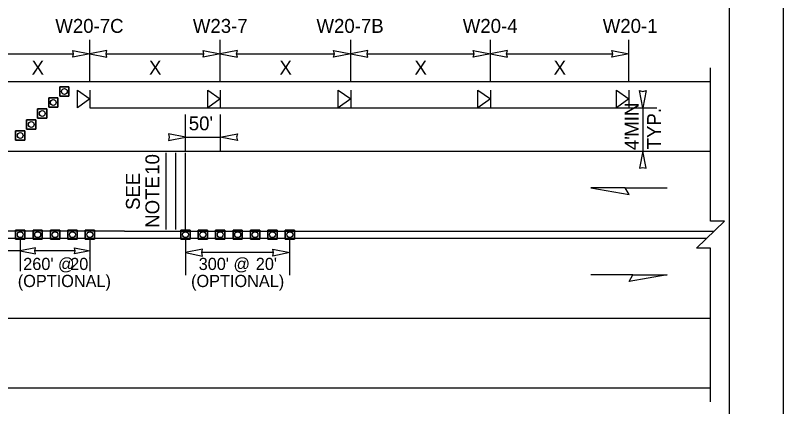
# Model space of a CAD drawing. Extents: x 99999.1 to 100095.7, y 99995 to 100010.7.
# Drawn here: x 100011.645 to 100016.062, y 100005.624 to 100007.873 of the extents above; entities that cross this region are included whole.
import ezdxf

# ---------------------------------------------------------------- set-up
doc = ezdxf.new("R2010")
doc.units = 0
for name, color, linetype in [('RD_ED_ShoulderPavedEdge', 7, 'Continuous'), ('RD_MK_LineDblYellowCenter', 7, 'Continuous'), ('RD_MK_LineEdgeWhite', 7, 'Continuous'), ('RD_MK_LineNoPass', 7, 'Continuous'), ('RD_MK_LineSkipCenter', 7, 'Continuous'), ('SH_GI_PlotLimits', 7, 'Continuous'), ('SH_GI_SheetBorder', 7, 'Continuous'), ('TR_SN_ConstructionSigns', 7, 'Continuous'), ('TR_WZ_PortableSignMountBlk-Org', 7, 'Continuous'), ('TR_WZ_TrafficCone', 7, 'Continuous'), ('TR_WZ_WorkZoneDetails', 7, 'Continuous'), ('TR_WZ_WorkZoneTextCurrent', 7, 'Continuous')]:
    doc.layers.add(name, color=color, linetype=linetype)

msp = doc.modelspace()

# ---------------------------------------------------------------- linework, layer by layer
at = {"layer": 'RD_ED_ShoulderPavedEdge'}
for p, q in [((100000.1076, 100007.4923), (100015.6424, 100007.4923)), ((100000.1076, 100005.7323), (100015.6424, 100005.7323))]:
    msp.add_line(p, q, dxfattribs=at)
at = {"layer": 'RD_MK_LineDblYellowCenter'}
for p, q in [((100012.2733, 100006.6323), (100015.6631, 100006.6323)), ((100012.2733, 100006.5923), (100015.6218, 100006.5923))]:
    msp.add_line(p, q, dxfattribs=at)
at = {"layer": 'RD_MK_LineEdgeWhite'}
for p, q in [((100000.1076, 100007.0923), (100015.6424, 100007.0923)), ((100000.1076, 100006.1323), (100015.6424, 100006.1323))]:
    msp.add_line(p, q, dxfattribs=at)
at = {"layer": 'RD_MK_LineNoPass'}
msp.add_line((100011.4733, 100006.5923), (100012.2733, 100006.5923), dxfattribs=at)
at = {"layer": 'RD_MK_LineSkipCenter'}
msp.add_lwpolyline([(100012.2733, 100006.6323), (100011.4733, 100006.6323)], dxfattribs=at)
at = {"layer": 'SH_GI_PlotLimits'}
msp.add_lwpolyline([(99999.0625, 99999.6875), (100016.0625, 99999.6875), (100016.0625, 100010.6875), (99999.0625, 100010.6875)], close=True, dxfattribs=at)
at = {"layer": 'SH_GI_SheetBorder'}
msp.add_line((100015.75, 100010.375), (100015.75, 100000), dxfattribs=at)
at = {"layer": 'TR_WZ_PortableSignMountBlk-Org'}
for p, q in [((100012.0733, 100007.4422), (100012.0733, 100007.3422)), ((100012.8233, 100007.4422), (100012.8233, 100007.3422)), ((100013.5733, 100007.4422), (100013.5733, 100007.3422)), ((100014.3761, 100007.4422), (100014.3761, 100007.3422)), ((100015.1733, 100007.4422), (100015.1733, 100007.3422))]:
    msp.add_line(p, q, dxfattribs=at)
for points in [[(100012.0733, 100007.3923), (100012.0015, 100007.3422), (100012.0015, 100007.4422)], [(100012.8233, 100007.3923), (100012.7515, 100007.3422), (100012.7515, 100007.4422)], [(100013.5733, 100007.3923), (100013.5015, 100007.3422), (100013.5015, 100007.4422)], [(100014.3761, 100007.3923), (100014.3042, 100007.3422), (100014.3042, 100007.4422)], [(100015.1733, 100007.3923), (100015.1015, 100007.3422), (100015.1015, 100007.4422)]]:
    msp.add_lwpolyline(points, close=True, dxfattribs=at)
at = {"layer": 'TR_WZ_TrafficCone'}
for points in [[(100011.9533, 100007.4623), (100011.9, 100007.4623), (100011.9, 100007.409), (100011.9533, 100007.409), (100011.9533, 100007.4623)], [(100011.9533, 100007.409), (100011.9, 100007.409), (100011.9, 100007.4623), (100011.9533, 100007.4623), (100011.9533, 100007.409)], [(100011.89, 100007.399), (100011.8367, 100007.399), (100011.8367, 100007.3457), (100011.89, 100007.3457), (100011.89, 100007.399)], [(100011.89, 100007.3457), (100011.8367, 100007.3457), (100011.8367, 100007.399), (100011.89, 100007.399), (100011.89, 100007.3457)], [(100011.8267, 100007.3357), (100011.7733, 100007.3357), (100011.7733, 100007.2823), (100011.8267, 100007.2823), (100011.8267, 100007.3357)], [(100011.8267, 100007.2823), (100011.7733, 100007.2823), (100011.7733, 100007.3357), (100011.8267, 100007.3357), (100011.8267, 100007.2823)], [(100011.7633, 100007.219), (100011.71, 100007.219), (100011.71, 100007.2723), (100011.7633, 100007.2723), (100011.7633, 100007.219)], [(100011.7633, 100007.2723), (100011.71, 100007.2723), (100011.71, 100007.219), (100011.7633, 100007.219), (100011.7633, 100007.2723)], [(100011.7, 100007.1557), (100011.6467, 100007.1557), (100011.6467, 100007.209), (100011.7, 100007.209), (100011.7, 100007.1557)], [(100011.7, 100007.209), (100011.6467, 100007.209), (100011.6467, 100007.1557), (100011.7, 100007.1557), (100011.7, 100007.209)], [(100011.7, 100006.639), (100011.6467, 100006.639), (100011.6467, 100006.5857), (100011.7, 100006.5857), (100011.7, 100006.639)], [(100011.7, 100006.5857), (100011.6467, 100006.5857), (100011.6467, 100006.639), (100011.7, 100006.639), (100011.7, 100006.5857)], [(100011.8, 100006.639), (100011.7467, 100006.639), (100011.7467, 100006.5857), (100011.8, 100006.5857), (100011.8, 100006.639)], [(100011.8, 100006.5857), (100011.7467, 100006.5857), (100011.7467, 100006.639), (100011.8, 100006.639), (100011.8, 100006.5857)], [(100011.9, 100006.639), (100011.8467, 100006.639), (100011.8467, 100006.5857), (100011.9, 100006.5857), (100011.9, 100006.639)], [(100011.9, 100006.5857), (100011.8467, 100006.5857), (100011.8467, 100006.639), (100011.9, 100006.639), (100011.9, 100006.5857)], [(100012, 100006.639), (100011.9467, 100006.639), (100011.9467, 100006.5857), (100012, 100006.5857), (100012, 100006.639)], [(100012, 100006.5857), (100011.9467, 100006.5857), (100011.9467, 100006.639), (100012, 100006.639), (100012, 100006.5857)], [(100012.1, 100006.639), (100012.0467, 100006.639), (100012.0467, 100006.5857), (100012.1, 100006.5857), (100012.1, 100006.639)], [(100012.1, 100006.5857), (100012.0467, 100006.5857), (100012.0467, 100006.639), (100012.1, 100006.639), (100012.1, 100006.5857)], [(100012.65, 100006.5857), (100012.5967, 100006.5857), (100012.5967, 100006.639), (100012.65, 100006.639), (100012.65, 100006.5857)], [(100012.65, 100006.639), (100012.5967, 100006.639), (100012.5967, 100006.5857), (100012.65, 100006.5857), (100012.65, 100006.639)], [(100012.75, 100006.5857), (100012.6967, 100006.5857), (100012.6967, 100006.639), (100012.75, 100006.639), (100012.75, 100006.5857)], [(100012.75, 100006.639), (100012.6967, 100006.639), (100012.6967, 100006.5857), (100012.75, 100006.5857), (100012.75, 100006.639)], [(100012.85, 100006.5857), (100012.7967, 100006.5857), (100012.7967, 100006.639), (100012.85, 100006.639), (100012.85, 100006.5857)], [(100012.85, 100006.639), (100012.7967, 100006.639), (100012.7967, 100006.5857), (100012.85, 100006.5857), (100012.85, 100006.639)], [(100012.95, 100006.5857), (100012.8967, 100006.5857), (100012.8967, 100006.639), (100012.95, 100006.639), (100012.95, 100006.5857)], [(100012.95, 100006.639), (100012.8967, 100006.639), (100012.8967, 100006.5857), (100012.95, 100006.5857), (100012.95, 100006.639)], [(100013.05, 100006.5857), (100012.9967, 100006.5857), (100012.9967, 100006.639), (100013.05, 100006.639), (100013.05, 100006.5857)], [(100013.05, 100006.639), (100012.9967, 100006.639), (100012.9967, 100006.5857), (100013.05, 100006.5857), (100013.05, 100006.639)], [(100013.15, 100006.5857), (100013.0967, 100006.5857), (100013.0967, 100006.639), (100013.15, 100006.639), (100013.15, 100006.5857)], [(100013.15, 100006.639), (100013.0967, 100006.639), (100013.0967, 100006.5857), (100013.15, 100006.5857), (100013.15, 100006.639)], [(100013.25, 100006.5857), (100013.1967, 100006.5857), (100013.1967, 100006.639), (100013.25, 100006.639), (100013.25, 100006.5857)], [(100013.25, 100006.639), (100013.1967, 100006.639), (100013.1967, 100006.5857), (100013.25, 100006.5857), (100013.25, 100006.639)]]:
    msp.add_lwpolyline(points, dxfattribs=at)
for centre in [(100011.9267, 100007.4357), (100011.8633, 100007.3723), (100011.8, 100007.309), (100011.7367, 100007.2457), (100011.6733, 100007.1823), (100011.6733, 100006.6123), (100011.7733, 100006.6123), (100011.8733, 100006.6123), (100011.9733, 100006.6123), (100012.0733, 100006.6123), (100012.6233, 100006.6123), (100012.7233, 100006.6123), (100012.8233, 100006.6123), (100012.9233, 100006.6123), (100013.0233, 100006.6123), (100013.1233, 100006.6123), (100013.2233, 100006.6123)]:
    msp.add_circle(centre, 0.0167, dxfattribs=at)
at = {"layer": 'TR_WZ_WorkZoneDetails'}
for p, q in [((100012.0733, 100007.4923), (100012.0733, 100007.7323)), ((100012.8233, 100007.4923), (100012.8233, 100007.7323)), ((100013.5733, 100007.4923), (100013.5733, 100007.7323)), ((100014.3761, 100007.4923), (100014.3761, 100007.7323)), ((100015.1733, 100007.4921), (100015.1733, 100007.7323)), ((100011.5671, 100007.6523), (100011.9796, 100007.6523)), ((100012.1671, 100007.6523), (100012.7296, 100007.6523)), ((100012.9171, 100007.6523), (100013.4796, 100007.6523)), ((100013.6671, 100007.6523), (100014.2823, 100007.6523)), ((100014.4698, 100007.6523), (100015.0796, 100007.6523)), ((100012.0733, 100007.3422), (100015.1733, 100007.3422)), ((100015.1733, 100007.3422), (100015.3333, 100007.3422)), ((100015.2533, 100007.3422), (100015.2533, 100007.0923)), ((100012.6233, 100007.0923), (100012.6233, 100007.3023)), ((100012.8233, 100007.3023), (100012.8233, 100007.0923)), ((100012.6233, 100007.1723), (100012.8233, 100007.1723)), ((100012.5128, 100006.6423), (100012.5128, 100007.0823)), ((100012.5685, 100006.6423), (100012.5685, 100007.0823)), ((100012.6233, 100006.6423), (100012.6233, 100007.0823)), ((100015.1733, 100007.0923), (100015.3333, 100007.0923)), ((100015.1513, 100006.8816), (100015.3924, 100006.8816)), ((100011.6733, 100006.5857), (100011.6733, 100006.4023)), ((100012.0733, 100006.5857), (100012.0733, 100006.4023)), ((100012.6233, 100006.589), (100012.6233, 100006.379)), ((100013.2233, 100006.379), (100013.2233, 100006.589)), ((100011.6733, 100006.5193), (100011.4933, 100006.5193)), ((100011.989, 100006.5193), (100011.7577, 100006.5193)), ((100013.1296, 100006.509), (100012.7171, 100006.509)), ((100015.1959, 100006.3816), (100014.9548, 100006.3816))]:
    msp.add_line(p, q, dxfattribs=at)
for points in [[(100012.0733, 100007.6523), (100011.9751, 100007.6331), (100011.9796, 100007.6523), (100011.9751, 100007.6716)], [(100012.0733, 100007.6523), (100012.1716, 100007.6331), (100012.1671, 100007.6523), (100012.1716, 100007.6716)], [(100012.8233, 100007.6523), (100012.7251, 100007.6331), (100012.7296, 100007.6523), (100012.7251, 100007.6716)], [(100012.8233, 100007.6523), (100012.9216, 100007.6331), (100012.9171, 100007.6523), (100012.9216, 100007.6716)], [(100013.5733, 100007.6523), (100013.4751, 100007.6331), (100013.4796, 100007.6523), (100013.4751, 100007.6716)], [(100013.5733, 100007.6523), (100013.6716, 100007.6331), (100013.6671, 100007.6523), (100013.6716, 100007.6716)], [(100014.3761, 100007.6523), (100014.2778, 100007.6331), (100014.2823, 100007.6523), (100014.2778, 100007.6716)], [(100014.3761, 100007.6523), (100014.4743, 100007.6331), (100014.4698, 100007.6523), (100014.4743, 100007.6716)], [(100015.1733, 100007.6523), (100015.0751, 100007.6331), (100015.0796, 100007.6523), (100015.0751, 100007.6716)], [(100015.2533, 100007.3422), (100015.2341, 100007.4405), (100015.2533, 100007.436), (100015.2726, 100007.4405)], [(100012.6233, 100007.1723), (100012.5251, 100007.1916), (100012.5296, 100007.1723), (100012.5251, 100007.1531)], [(100012.8233, 100007.1723), (100012.9216, 100007.1916), (100012.9171, 100007.1723), (100012.9216, 100007.1531)], [(100015.2533, 100007.0923), (100015.2341, 100006.9941), (100015.2533, 100006.9986), (100015.2726, 100006.9941)], [(100014.9548, 100006.8816), (100015.1736, 100006.843), (100015.1513, 100006.8816)], [(100011.6733, 100006.5193), (100011.7618, 100006.502), (100011.7577, 100006.5193), (100011.7618, 100006.5367)], [(100012.0733, 100006.5193), (100011.9849, 100006.502), (100011.989, 100006.5193), (100011.9849, 100006.5367)], [(100012.6233, 100006.509), (100012.7216, 100006.4897), (100012.7171, 100006.509), (100012.7216, 100006.5283)], [(100013.2233, 100006.509), (100013.1251, 100006.4897), (100013.1296, 100006.509), (100013.1251, 100006.5283)], [(100015.3924, 100006.3816), (100015.1736, 100006.343), (100015.1959, 100006.3816)]]:
    msp.add_lwpolyline(points, close=True, dxfattribs=at)
msp.add_lwpolyline([(100015.6424, 100005.6523), (100015.6424, 100006.5349), (100015.5624, 100006.5349), (100015.7225, 100006.6898), (100015.6424, 100006.6898), (100015.6424, 100007.5723)], dxfattribs=at)

# ---------------------------------------------------------------- texts
at = {"layer": 'TR_SN_ConstructionSigns'}
for s, p in [('W20-7C', (100011.8748, 100007.7723)), ('W23-7', (100012.6656, 100007.7723)), ('W20-7B', (100013.3763, 100007.7723)), ('W20-4', (100014.2176, 100007.7723)), ('W20-1', (100015.0224, 100007.7723))]:
    msp.add_text(s, height=0.08, rotation=360, dxfattribs=at).set_placement(p)
at = {"layer": 'TR_WZ_WorkZoneDetails'}
for s, p in [('10', (100012.4728, 100006.9566)), ('SEE', (100012.3608, 100006.7544)), ('NOTE', (100012.4728, 100006.6518))]:
    msp.add_text(s, height=0.08, rotation=90, dxfattribs=at).set_placement(p)
at = {"layer": 'TR_WZ_WorkZoneTextCurrent'}
for s, height, p in [('X', 0.08, (100011.7386, 100007.5323)), ('X', 0.08, (100012.4136, 100007.5323)), ('X', 0.08, (100013.1636, 100007.5323)), ('X', 0.08, (100013.94, 100007.5323)), ('X', 0.08, (100014.74, 100007.5323)), ("50'", 0.08, (100012.6421, 100007.2123)), ("260' @", 0.07, (100011.6903, 100006.4093)), ("20'", 0.07, (100011.9604, 100006.4093)), ("300' @", 0.07, (100012.6991, 100006.4093)), ("20'", 0.07, (100013.0275, 100006.4093)), ('(OPTIONAL)', 0.07, (100011.659, 100006.3113)), ('(OPTIONAL)', 0.07, (100012.6553, 100006.3113))]:
    msp.add_text(s, height=height, dxfattribs=at).set_placement(p)
for s, p in [('MIN', (100015.2293, 100007.1754)), ('TYP.', (100015.3573, 100007.1026)), ("4'", (100015.2293, 100007.0989))]:
    msp.add_text(s, height=0.08, rotation=90, dxfattribs=at).set_placement(p)

doc.saveas('drawing.dxf')
